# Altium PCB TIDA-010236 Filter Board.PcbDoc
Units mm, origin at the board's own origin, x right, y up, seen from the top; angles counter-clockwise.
Board outline 135 x 47 mm, 2 copper layers (Top Layer, Bottom Layer), stack 1.571 mm thick; 35 components, 11 nets, 54 pads, 100 vias.
Unrouted connection lines stored in the file: 9.
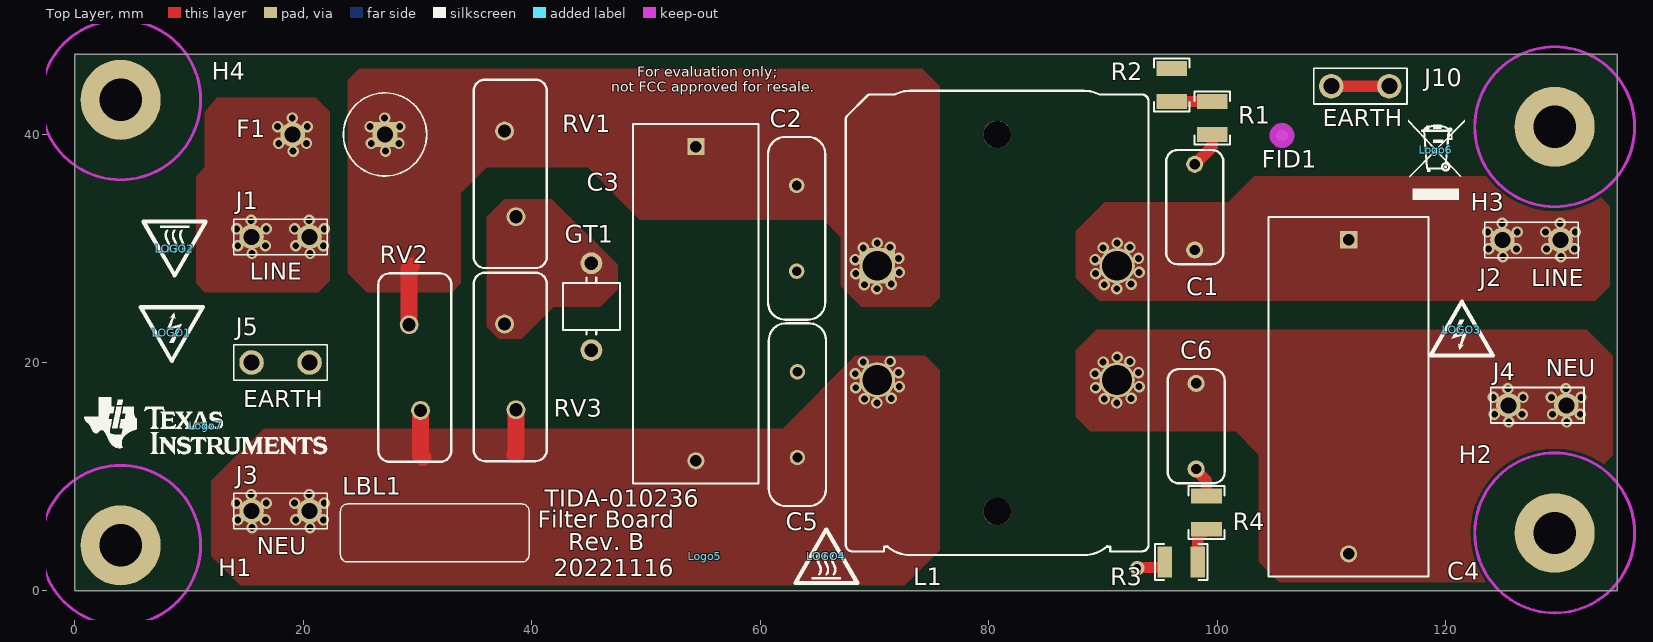
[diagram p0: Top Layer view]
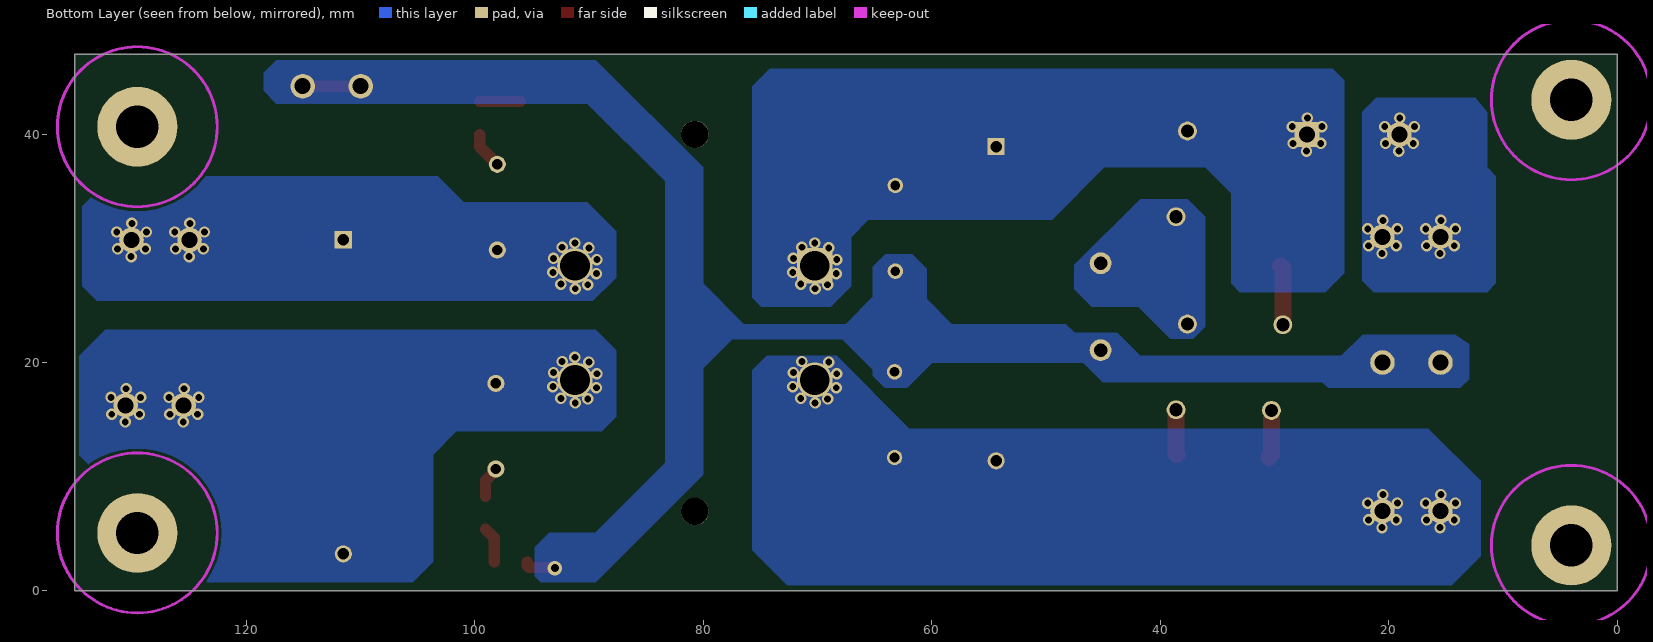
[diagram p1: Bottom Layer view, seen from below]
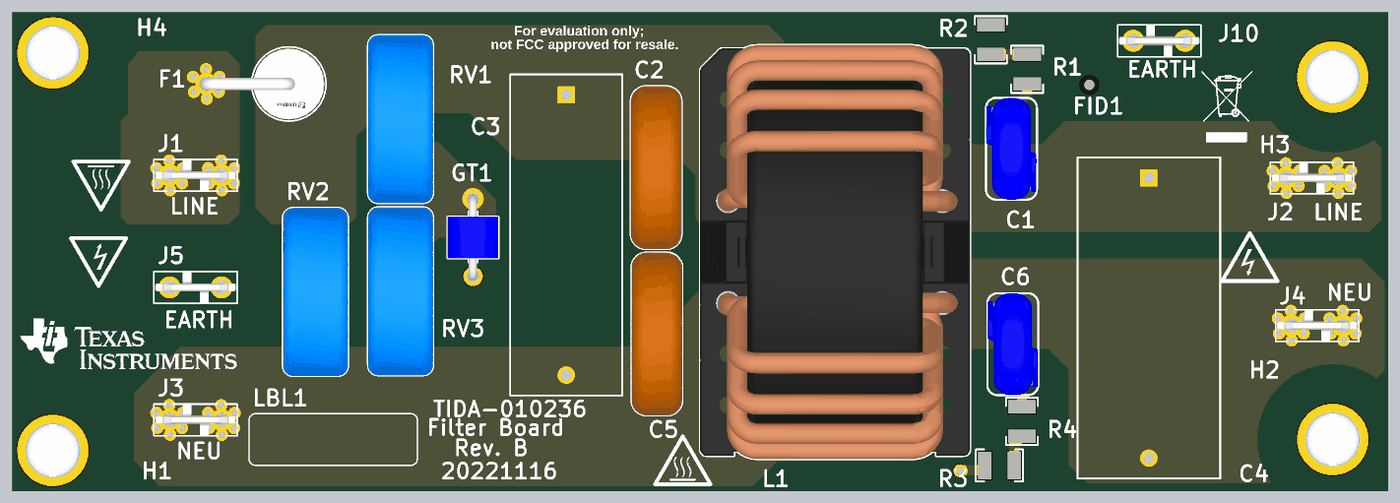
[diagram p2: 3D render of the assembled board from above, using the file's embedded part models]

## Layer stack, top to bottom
Top Solder: solder mask 0.0102, Solder Resist, Dk 3.5
Top Layer: signal copper 0.0356
Dielectric 1: dielectric 1.5, FR-4, Dk 4.8
Bottom Layer: signal copper 0.0356
Bottom Solder: solder mask 0.0102, Solder Resist, Dk 3.5

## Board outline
0,0 0,47 135,47 135,0

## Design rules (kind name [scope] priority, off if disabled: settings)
Clearance [All] p1: gap=0.254 ignorepadtopadclearanceinfootprint=FALSE except(0: Arc-Hole Track-Hole SMDPad-Hole THPad-Hole Via-Hole Fill-Hole Poly-Hole Region-Hole Text-Hole)
HoleSize [All] p1: absolutevalues=TRUE maxlimit=5 minlimit=0.025 maxpercent=80.000 minpercent=20.000
PlaneConnect [All] p1: planeconnectstyle=Direct reliefexpansion=0.508 reliefentries=4 reliefconductorwidth=0.5 reliefairgap=0.254
PolygonConnect [All] p1: connectstyle=Direct reliefconductorwidth=0.5 reliefentries=4 polygonreliefangle="90 Angle" airgapwidth=0.254
RoutingVias [All] p1: holewidth=0.711 width=1.27 viastyle="Through Hole" minholewidth=0.711 minwidth=1.27 maxholewidth=0.711 maxwidth=1.27
SolderMaskExpansion [All] p1: expansion=0.102 istentingtop=FALSE
Width [All] p1: maxlimit=5.08 minlimit=0.254 preferedwidth=2.032 minimp=50.000000 maximp=50.000000 favimp=50.000000
28 further rules are at their usual default settings.

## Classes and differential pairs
net class HV: NetC1_1 NetC2_1 NetF1_2

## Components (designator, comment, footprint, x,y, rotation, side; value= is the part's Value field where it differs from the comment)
C1 "DE2E3KY472MB3BM02F" KY_1000x500x1300 98.028,33.604 r90 top value=4700pF
C2 "VY2103M63Y5US63V7" VY2_1600x500 63.179,31.75 r270 top value=0.01uF
C3 "B32924C3105M" B32924_19mm 54.356,25.146 r270 top value=1uF
C4 "B32924C3225K" B32924_24.5mm 111.506,17 r270 top value=2.2uF
C5 "VY2103M63Y5US63V7" VY2_1600x500 63.246,15.434 r270 top value=0.01uF
C6 "DE2E3KY472MB3BM02F" KY_1000x500x1300 98.155,14.427 r90 top value=4700pF
F1 "0524025" FP-0525025.MXEP_vm_AXIAL-MFG 27.146,39.964 r180 top
FID1 "Fiducial" Fiducial10-20 105.664,39.878 r270 top
GT1 "2035-20-B5" GasTube_2035-20-B5 45.212,24.892 r90 top value=200V
H1 "29311" Keystone29311 4,4 r180 top
H2 "29311" Keystone29311 129.54,5.08 r180 top
H3 "29311" Keystone29311 129.54,40.64 r180 top
H4 "29311" Keystone29311 4,43 r180 top
J1 "63824-1" FP-63824-1_CONN_7MM92_3MM11-MFG 18,31 r180 top
J2 "63824-1" FP-63824-1_CONN_7MM92_3MM11-MFG 127.508,30.734 r0 top
J3 "63824-1" FP-63824-1_CONN_7MM92_3MM11-MFG 18,7 r0 top
J4 "63824-1" FP-63824-1_CONN_7MM92_3MM11-MFG 128.016,16.256 r180 top
J5 "63824-1" FP-63824-1_CONN_7MM92_3MM11-MFG 18,20 r180 top
J10 "63824-1" FP-63824-1_CONN_7MM92_3MM11-MFG 112.522,44.196 r180 top
L1 "7448062105" WE-CMBNC_XXL 80.731,23.464 r0 top value=5mH
LBL1 "THT-14-423-10" Label_650x200 31.496,5.08 r0 top
LOGO1 "DANGER HIGH VOLTAGE" IEC_HighVoltage_Small 8.481,22.606 r180 top
LOGO2 "CAUTION HOT SURFACE" IEC_HotSurface_Small 8.722,29.972 r180 top
LOGO3 "DANGER HIGH VOLTAGE" IEC_HighVoltage_Small 121.412,22.86 r0 top
LOGO4 "CAUTION HOT SURFACE" IEC_HotSurface_Small 65.786,3.048 r0 top
Logo5 "FCC disclaimer" FCC_disclaimer_stacked 55.118,3.058 r0 top
Logo6 "WEEE logo" WEEE_Minimum 119.126,38.608 r0 top
Logo7 "Texas Instruments" TI_Stacked_Overlay_Small 11.44,14.478 r0 top
R1 "RC1210JR-0739RL" 1210 99.568,41.402 r270 top value=39
R2 "RC1210JR-0739RL" 1210 96.012,44.302 r90 top value=39
R3 "RC1210JR-0739RL" 1210 96.848,2.54 r0 top value=39
R4 "RC1210JR-0739RL" 1210 99.06,6.858 r90 top value=39
RV1 "MOV-14D471K" Bourns_MOV-14D621K 38.108,36.516 r90 top
RV2 "MOV-14D471K" Bourns_MOV-14D621K 29.754,19.558 r90 top
RV3 "MOV-14D471K" Bourns_MOV-14D621K 38.108,19.618 r90 top

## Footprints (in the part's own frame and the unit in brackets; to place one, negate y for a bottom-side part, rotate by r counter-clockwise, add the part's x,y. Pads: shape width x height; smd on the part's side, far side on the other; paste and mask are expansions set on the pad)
1210 [mm] "1210 from SM-752 data"
  rect 1.3x2.7 smd: 1(-1.45,0) 2(1.45,0)
  silkscreen extent -2.32,-1.57 2.32,1.57, body extent -1.7,-1.35 1.7,1.35, height 1.35
B32924_19mm [mm] "Epcos film capacitors, 27.5mm spacing"
  rect 1.5x1.5 hole 1: 1(-13.75,0)
  round 1.5 hole 1: 2(13.75,0)
  silkscreen extent -15.75,-5.5 15.75,5.5, body extent -15.75,-5.5 15.75,5.5, height 19
B32924_24.5mm [mm] "Epcos film capacitors, 27.5mm spacing"
  rect 1.5x1.5 hole 1: 1(-13.75,0)
  round 1.5 hole 1: 2(13.75,0)
  silkscreen extent -15.75,-7 15.75,7, body extent -15.75,-7 15.75,7, height 24.5
Bourns_MOV-14D621K [mm] "TH, 2-Leads, Dia 16.5mm"
  round 1.65 hole 1.15: 1(-3.75,-0.5) 2(3.75,0.5)
  silkscreen extent -8.25,-3.2 8.25,3.2, body extent -8.25,-3.2 8.25,3.2, height 21.97
FCC_disclaimer_stacked [mm]
Fiducial10-20 [mm]
  round 1 smd mask+0.5: 1(0,0)
  Top Layer keep-out circle w1.178: c0,0 r0.5
FP-63824-1_CONN_7MM92_3MM11-MFG [mm]
  round 2.15 hole 1.4 paste-1000 mask+0: 1(-2.54,0) 1(2.54,0)
  silkscreen extent -4.09,-1.56 4.09,1.56, body extent -3.96,-1.54 3.96,1.54, height 10.88
FP-0525025.MXEP_vm_AXIAL-MFG [mm]
  rrect5% 2.15x2.15 hole 1.4 paste-1000 mask+0: 1(0,0)
  round 2.15 hole 1.4 paste-1000 mask+0: 2(8.092,0)
  silkscreen extent -3.64,-3.64 3.64,3.64, body extent -3.74,-3.74 9.27,3.74, height 0.25
GasTube_2035-20-B5 [mil] "Bourns Gas Disharge Tube, 5mm Diameter"
  round 75 hole 47: 1(-150,0) 2(149.61,0)
  silkscreen extent -96,-98 100,98, body extent -166,-97 166,99, height 197
IEC_HighVoltage_Small [mm]
  silkscreen extent -2.72,-2.24 2.72,2.47
IEC_HotSurface_Small [mm]
  silkscreen extent -2.72,-2.36 2.72,2.35
Keystone29311 [mm] "Srcew, Pan HeadM5x0.5 mm, Zinc Plated  6.0mm L"
  round 7 / inner round 4.9 / far side round 7 hole 3.7: 1(0,0)
  body extent -2.7,-2.7 2.7,2.7, height 1.72
KY_1000x500x1300 [mm] "MuRata"
  round 1.5 hole 0.9: 1(-3.75,0) 2(3.75,0)
  silkscreen extent -5,-2.5 5,2.5, body extent -5,-2.5 5,2.5, height 13
Label_650x200 [mil] "Thermal Transfer Label"
  round 1 on Mech13: 0(0,0)
  silkscreen extent -325,-100 325,100, body extent -325,-100 325,100, height 1
TI_Stacked_Overlay_Small [mm]
  silkscreen extent -10.63,-2.49 10.63,2.49
VY2_1600x500 [mm] "TH, 2-Leads, 16x5mm, Pin Spacing 7.5mm"
  round 1.35 hole 0.85: 1(-3.75,0) 2(3.75,0)
  silkscreen extent -8,-2.5 8,2.5, body extent -7.97,-2.5 8,2.5, height 19.99
WE-CMBNC_XXL [mm] "TH, 4-Leads, Body 48x27mm"
  rect 3.1x3.1 hole 2.6: 1(-10.5,5)
  round 3.1 hole 2.6: 2(-10.5,-5) 3(10.5,-5) 4(10.5,5)
  round 2.4 hole 2.4 unplated mask+0: MH1(0,16.5) MH2(0,-16.5)
  silkscreen extent -13.25,-20.32 13.25,20.32, body extent -13.25,-20.32 13.25,20.32, height 39.1
WEEE_Minimum [mm] "WEEElie bin"
  silkscreen extent -2.42,-4.38 2.52,2.65

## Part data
C1 C6: library part CMP-0009611-1, "CAP, CERM, 4700 pF, 250 V, +/- 20%, E, 10x5x13mm", Cap_Case=10x5x13mm, Manufacturer=MuRata, Supplier Part Number 1=490-9484-ND, TempCo=E, Tolerance_%=20%, Value1=Unknown, Value2=250V, ValueDisplayed=4700pF
C2 C5: library part CMP-0009626-1, "CAP, CERM, 0.01 uF, 440 V, +/- 20%, Y5U, D16xT5mm", Cap_Case=16x5mm, Manufacturer=Vishay-Bccomponents, Supplier Part Number 1=BC2361-ND, TempCo=Y5U, Tolerance_%=20%, Value1=Unknown, Value2=440V, ValueDisplayed=0.01uF
C3: library part CMP-0012432-3, "CAP, Film, 1 uF, 630 V, +/- 20%, 0.018 ohm, TH", Manufacturer=Wurth, PartNumber=890334027009, Tolerance_%=20%, Value1="0.018 ohm", Value2=630V, ValueDisplayed=1uF
C4: library part CMP-0012435-3, "CAP, Film, 2.2 uF, 630 V, +/- 10%, TH", Manufacturer=WURTH, PartNumber=890334027021CS, Supplier Part Number 1=732-11875-ND, Tolerance_%=10%, Value1=Unknown, Value2=630V, ValueDisplayed=2.2uF
F1: library part CMP-4956-0000-1, "FUSE CERM 25A 250VAC 125VDC 3AB", Digikey Part Number=F3332-ND, Fuse Current=25A, Fuse Interrupt Dc Current=10000A, Manufacturer=Littelfuse, Mouser Part Number=576-0324025.MXP, Operating Temperature Range="-55°C to +125°C", Part Number=0324025.MXP, Supplier Part Number 1=F10249-ND
FID1: library part CMP-0077181-1, "Fiducial mark.  There is nothing to buy or mount.", Manufacturer=N/A
GT1: library part CMP-0001871-2, "Gas Discharge Tube, 2-Pole, TH", Manufacturer=Bourns, Supplier Part Number 1=2035-20-B5-ND
H1 H2 H3 H4: library part CMP-0003639-1, "Screw Pan Head M3", Manufacturer=Keystone, Supplier Part Number 1=36-29311-ND
J1 J2 J3 J4 J5 J10: library part CMP-0089624-1, Current_A=20A, Digikey Part Number=A29938CT-ND, Manufacturer="TE Connectivity", Mouser Part Number=571-638241, Operating Temperature Range="-40°C to +105°C"
L1: library part CMP-0013070-2, "Coupled inductor, 5 mH,  A, 0.0065 ohm, TH", Manufacturer="Wurth Elektronik", Supplier Part Number 1=732-5607-ND, ValueDisplayed=5mH
LBL1: library part CMP-0003625-1, "Thermal Transfer Printable Labels, 0.650\" W x 0.200\" H - 10,000 per roll", Manufacturer=Brady, Supplier Part Number 1=97C5133
LOGO1 LOGO3: library part CMP-0074835-1, "IEC 61010-1 High Voltage Warning"
LOGO2 LOGO4: library part CMP-0074837-1, "IEC 61010-1 Hot Surface Warning"
Logo5: library part CMP-0074847-1, "FCC_disclaimer"
Logo6: library part CMP-0074769-1
Logo7: library part CMP-0074838-1, "Texas Instrument Corporate Signature"
R1 R2 R3 R4: library part CMP-0083539-1, "RES, 39, 5%, 0.5 W, 1210", Manufacturer=Yageo, Power_W=500mW, TempCo="100 ppm/C", Tolerance_%=5%, Value2=0.5W, Value_Code=39R0, ValueDisplayed=39
RV1 RV2 RV3: library part CMP-0001785-2, "VARISTOR 558V 4.5KA, TH", Manufacturer=WURTH, PartNumber=820543011, Supplier Part Number 1=732-13277-1-ND

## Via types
v1: diameter 1, hole 0.6, Top Layer to Bottom Layer, 99 vias
v2: diameter 1.27, hole 0.711, Top Layer to Bottom Layer, 1 vias

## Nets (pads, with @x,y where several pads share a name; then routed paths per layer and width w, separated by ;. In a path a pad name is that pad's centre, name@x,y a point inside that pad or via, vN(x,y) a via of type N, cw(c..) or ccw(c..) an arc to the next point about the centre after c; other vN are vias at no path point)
EARTH: C2.2 C5.1 GT1.1 J5.1 J10.1 R2.2 R3.1 | length 8.2
  Top Layer w1: C2.2 C2.2@63.246,27.933 ; v2(92.977,2.007) 93.028,2.058 95.248,2.058 95.398,2.208 R3.1 ; J10.1@109.837,44.196 109.982,44.196 J10.1@115.062,44.196
NetC1_1: C1.1 C4.1 J2.1 L1.4
  other v1: 91.206,26.464 90.106,26.814 92.456,26.864 89.356,27.789 93.156,27.889 89.306,29.014 93.106,29.114 125.008,29.277 130.088,29.277 123.758,29.952 126.183,29.952 128.838,29.952 131.263,29.952 90.006,30.039 92.356,30.089 91.231,30.464 123.658,31.427 126.258,31.427 128.738,31.427 131.338,31.427 124.933,32.177 130.013,32.177
NetC1_2: C1.2 R1.2 | length 3.2
  Top Layer w1: C1.2 99.568,38.894 R1.2
NetC2_1: C2.1 C3.1 F1.1 L1.1 RV1.2 RV2.2 | length 5.2
  Top Layer w1.5: RV2.2 29.254,28.238 29.464,28.448
  other v1: 70.206,26.464 69.106,26.814 71.456,26.864 68.356,27.789 72.156,27.889 68.306,29.014 72.106,29.114 69.006,30.039 71.356,30.089 70.231,30.464 27.186,38.507 25.936,39.182 28.361,39.182 25.836,40.657 28.436,40.657 27.111,41.407
NetC3_2: C3.2 C5.2 J3.1 L1.2 RV2.1 RV3.1 | length 8.2
  Top Layer w1.5: RV2.1 30.254,11.91 30.48,11.684 ; 38.551,11.946 38.608,12.004 RV3.1
  other v1: 15.5,5.543 20.58,5.543 14.25,6.218 16.675,6.218 19.33,6.218 21.755,6.218 14.15,7.693 16.75,7.693 19.23,7.693 21.83,7.693 15.425,8.443 20.505,8.443 70.206,16.464 69.106,16.814 71.456,16.864 68.356,17.789 72.156,17.889 68.306,19.014 72.106,19.114 69.006,20.039 71.356,20.089
NetC4_2: C4.2 C6.2 J4.1 L1.3
  other v1: 125.516,14.799 130.596,14.799 124.266,15.474 126.691,15.474 129.346,15.474 131.771,15.474 91.206,16.464 90.106,16.814 92.456,16.864 124.166,16.949 126.766,16.949 129.246,16.949 131.846,16.949 125.441,17.699 130.521,17.699 89.356,17.789 93.156,17.889 89.306,19.014 93.106,19.114 90.006,20.039 92.356,20.089 91.231,20.464
NetC6_1: C6.1 R4.2 | length 2.7
  Top Layer w1: C6.1 98.155,10.557 99.06,9.652 R4.2
NetF1_2: F1.2 J1.1
  other v1: 15.5,29.543 20.58,29.543 14.25,30.218 16.675,30.218 19.33,30.218 21.755,30.218 14.15,31.693 16.75,31.693 19.23,31.693 21.83,31.693 15.425,32.443 20.505,32.443 19.094,38.507 17.844,39.182 20.269,39.182 17.744,40.657 20.344,40.657 19.019,41.407
NetGT1_2: GT1.2 RV1.1 RV3.2
NetR1_1: R1.1 R2.1 | length 3.6
  Top Layer w1: R2.1 R1.1
NetR3_2: R3.2 R4.1 | length 3.2
  Top Layer w1: R3.2 98.298,4.646 R4.1
pads on no net: FID1.1 H1.1 H2.1 H3.1 H4.1 L1.MH1 L1.MH2 LBL1.0

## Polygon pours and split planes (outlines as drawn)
NetC4_2 on Top Layer "Top Layer-NetC4_2" (solid, remove dead copper, pour order 20): 87.63,21.082 89.408,22.86 132.334,22.86 134.62,20.574 134.62,11.88 132.9,10.16 123.502,0.762 105.41,0.762 103.632,2.54 103.632,11.938 101.6,13.97 88.9,13.97 87.63,15.24
NetC1_1 on Top Layer "Top Layer-NetC1_1" (solid, remove dead copper, pour order 18): 87.63,27.422 87.63,31.496 90.17,34.036 100.965,34.036 103.251,36.322 124.46,36.322 125.73,35.052 132.998,35.052 134.366,33.684 134.366,26.67 133.096,25.4 89.662,25.4 87.884,27.178
NetGT1_2 on Top Layer "Top Layer-NetGT1_2" (solid, pour order 14): 37.338,34.036 37.592,34.29 41.749,34.29 47.498,28.541 47.498,26.416 45.974,24.892 41.91,24.892 39.116,22.098 37.084,22.098 36.068,23.114 36.068,32.758 36.838,33.528
NetC2_1 on Top Layer "Top Layer-NetC2_1" (solid, pour order 12): 23.876,27.813 25.527,26.162 33.02,26.162 33.782,26.924 33.782,34.798 36.068,37.084 44.885,37.084 49.457,32.512 65.532,32.512 67.056,30.988 67.056,26.67 68.834,24.892 74.93,24.892 75.692,25.654 75.692,44.196 74.168,45.72 24.892,45.72 23.876,44.704
NetF1_2 on Top Layer "Top Layer-NetF1_2" (solid, pour order 10): 11.382,41.913 11.382,37.084 10.62,36.322 10.62,26.924 11.382,26.162 21.288,26.162 22.304,27.178 22.304,35.306 22.304,41.958 21.082,43.18 12.395,43.18
NetC3_2 on Top Layer "Top Layer-NetC3_2" (solid, pour order 8): 11.938,3.048 14.478,0.508 42.672,0.508 72.644,0.508 75.692,3.556 75.692,19.304 74.422,20.574 68.326,20.574 61.976,14.224 16.51,14.224 11.938,9.652
EARTH on Bottom Layer "Bottom Layer-EARTH" (solid, pour order 67): 12.954,18.542 13.716,17.78 25.303,17.78 25.811,18.288 45.024,18.288 46.736,20 46.765,19.971 59.957,19.971 62.148,17.78 64.086,17.78 65.151,18.845 65.151,19.365 67.834,22.047 77.453,22.047 80.01,19.49 80.01,10.16 89.408,0.762 94.234,0.762 94.742,1.27 94.742,3.81 93.472,5.08 89.447,5.08 83.312,11.215 83.312,35.851 90.133,42.672 117.37,42.672 118.491,43.793 118.491,45.361 117.37,46.482 89.408,46.482 80.01,37.084 80.01,26.924 76.454,23.368 67.539,23.368 65.151,25.756 65.151,28.389 64.081,29.459 61.697,29.459 60.452,28.214 60.452,25.581 58.239,23.368 48.26,23.368 47.49,22.598 43.773,22.598 41.749,20.574 24.13,20.574 22.279,22.425 14.152,22.425 12.954,21.59
NetC4_2 on Bottom Layer "Top Layer-NetC4_2" (solid, remove dead copper, pour order 47): 87.63,21.082 89.408,22.86 132.334,22.86 134.62,20.574 134.62,11.88 132.9,10.16 123.502,0.762 105.41,0.762 103.632,2.54 103.632,11.938 101.6,13.97 88.9,13.97 87.63,15.24
NetC1_1 on Bottom Layer "Top Layer-NetC1_1" (solid, remove dead copper, pour order 46): 87.63,27.422 87.63,31.496 90.17,34.036 100.965,34.036 103.251,36.322 124.46,36.322 125.73,35.052 132.998,35.052 134.366,33.684 134.366,26.67 133.096,25.4 89.662,25.4 87.884,27.178
NetGT1_2 on Bottom Layer "Top Layer-NetGT1_2" (solid, pour order 45): 37.338,34.036 37.592,34.29 41.749,34.29 47.498,28.541 47.498,26.416 45.974,24.892 41.91,24.892 39.116,22.098 37.084,22.098 36.068,23.114 36.068,32.758 36.838,33.528
NetC2_1 on Bottom Layer "Top Layer-NetC2_1" (solid, pour order 44): 23.876,27.813 25.527,26.162 33.02,26.162 33.782,26.924 33.782,34.798 36.068,37.084 44.885,37.084 49.457,32.512 65.532,32.512 67.056,30.988 67.056,26.67 68.834,24.892 74.93,24.892 75.692,25.654 75.692,44.196 74.168,45.72 24.892,45.72 23.876,44.704
NetF1_2 on Bottom Layer "Top Layer-NetF1_2" (solid, pour order 43): 11.382,41.913 11.382,37.084 10.62,36.322 10.62,26.924 11.382,26.162 21.288,26.162 22.304,27.178 22.304,35.306 22.304,41.958 21.082,43.18 12.395,43.18
NetC3_2 on Bottom Layer "Top Layer-NetC3_2" (solid, pour order 42): 11.938,3.048 14.478,0.508 42.672,0.508 72.644,0.508 75.692,3.556 75.692,19.304 74.422,20.574 68.326,20.574 61.976,14.224 16.51,14.224 11.938,9.652

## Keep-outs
Keep-Out Layer:
  circle w0.254: c129.54,40.64 r7
  circle w0.254: c129.54,5.08 r7
  circle w0.254: c4,4 r7
  circle w0.254: c4,43 r7

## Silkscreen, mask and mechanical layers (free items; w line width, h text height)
Top Overlay:
  text "EARTH" at 109.22,40.687 h1.5
  text "LINE" at 15.3,27.25 h1.5
  text "LINE" at 127.508,26.67 h1.5
  text "NEU" at 128.778,18.796 h1.5
  text "EARTH" at 14.739,16.107 h1.5
  text "TIDA-010236" at 41.148,7.366 h1.5
  text "Filter Board" at 40.513,5.543 h1.5
  text "Rev. B" at 43.18,3.556 h1.5
  text "NEU" at 15.935,3.238 h1.5
  text "20221116" at 41.91,1.27 h1.5
Mechanical 1:
  the board outline again, w0.1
